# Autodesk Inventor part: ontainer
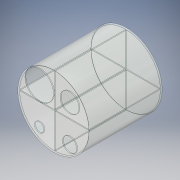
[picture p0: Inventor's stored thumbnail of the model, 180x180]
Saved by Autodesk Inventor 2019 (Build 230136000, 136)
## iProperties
Created: 2021-07
Part Number: ontainer
Material: Glass
Document SubType Name: Modeling
Designer: Avinash
Density: 2.18 g/cm^3
Appearance: Clear
Author: Avinash
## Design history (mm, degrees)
sketch "Sketch1"
  geometry: L1 (-75, 2)-(-74.973, 2); L2 (0, 73)-(0, 2); L3 (0, 0)-(0, -73); L4 (-72.973, 2)-(0, 2); L5 (-73, 0)-(0, 0); L6 (2, 0)-(73, 0); L7 (2, 2)-(72.973, 2); L8 (74.973, 2)-(75, 2); L9 (2, 0)-(2, -72.973); L10 (2, -74.973)-(2, -75); L11 (2, 75)-(2, 74.973); L12 (2, 72.973)-(2, 2); A1 r 75 centre (0, 0) between (-74.973, 2) and (74.973, 2); A2 r 73 centre (0, 0) between (0, 73) and (-72.973, 2); A3 r 73 centre (0, 0) between (-73, 0) and (0, -73); A4 r 73 centre (0, 0) between (2, -72.973) and (73, 0); A5 r 73 centre (0, 0) between (72.973, 2) and (2, 72.973); 1 further point
  constraints: 24 end point, 12 point on circle, 5 centre point, 2 horizontal, 1 coincident
  dimensions: "d0" = 150 diameter of A1
extrude "Extrusion3" new body sketch "Sketch1" distance "d7" = 150; taper "d8" = 0 deg
sketch "Sketch3"
  geometry: C1 r 75 at (0, 0); C2 r 30 at (-29.972, 32.293); C3 r 20 at (33.915, 32.293); C4 r 10 at (-29.972, -44.48); C5 r 15 at (33.915, -44.48); 1 further point
  constraints: 5 centre point, 1 coincident
  dimensions: "d9" = 60 diameter of C2; "d10" = 150 diameter of C1; "d11" = 40 diameter of C3; "d12" = 30 diameter of C5; "d13" = 20 diameter of C4
extrude "Extrusion4" join sketch "Sketch3" distance "d14" = 2; taper "d15" = 0 deg
sketch "Sketch4"
  geometry: C1 r 75 at (0, 0); 1 further point
  constraints: 1 centre point, 1 coincident
extrude "Extrusion5" join sketch "Sketch4" distance "d16" = 2; taper "d17" = 0 deg
body "Solid2"
